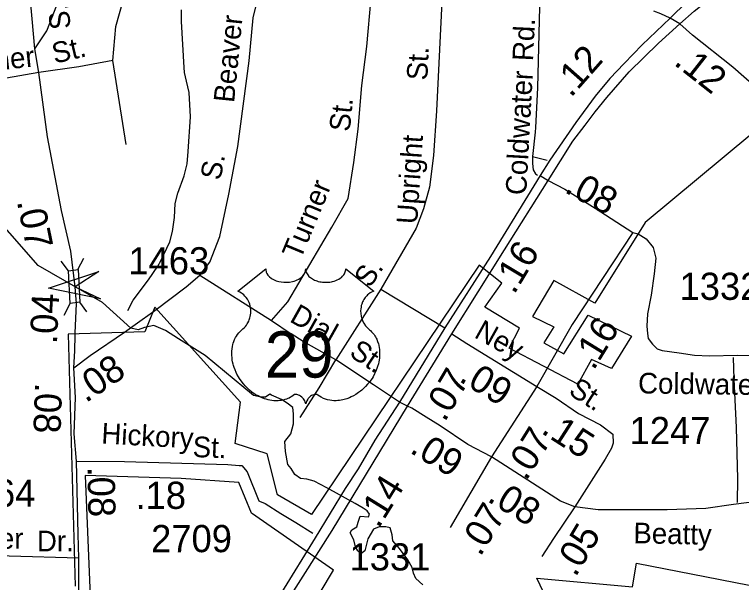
# Model space of a CAD drawing. Extents: x 1473865 to 1648260, y 639067 to 773536.
# Drawn here: x 1520496 to 1523838, y 653093 to 655704 of the extents above; entities that cross this region are included whole.
import ezdxf

# ---------------------------------------------------------------- set-up
doc = ezdxf.new("R2010")
doc.units = 0
for name, color, linetype in [('Exist Boundary Political City Limit New', 7, 'Continuous'), ('Exist Hydrographic Creek Single Shore', 7, 'Continuous'), ('Exist Hydrographic Misc Water Feature', 7, 'Continuous'), ('Exist Road Non-System Type 51', 7, 'Continuous'), ('Exist Road Non-System Type 51 Label', 7, 'Continuous'), ('Exist Road Primary US Divided Attributed', 7, 'Continuous'), ('Exist Road Primary US Mileage Hundredths English Label', 7, 'Continuous'), ('Exist Road Primary US Shield CELL', 7, 'Continuous'), ('Exist Road Primary US Shield Number Label', 7, 'Continuous'), ('Exist Road Secondary Mileage Hundredths English Label', 7, 'Continuous'), ('Exist Road Secondary Structure Standard Bridge Attributed CELL', 7, 'Continuous'), ('Exist Road Secondary Structure Standard Bridge CELL', 7, 'Continuous'), ('Exist Road Secondary Type 51 Attributed', 7, 'Continuous'), ('Exist Road Secondary Type 51 Label', 7, 'Continuous'), ('Exist Road Secondary Type 51 Number Label', 7, 'Continuous'), ('Map Preparation Boundary City Limit Buffer Line', 7, 'Continuous')]:
    doc.layers.add(name, color=color, linetype=linetype)

msp = doc.modelspace()

# ---------------------------------------------------------------- linework, layer by layer
at = {"layer": 'Exist Boundary Political City Limit New'}
for points in [[(1524121.9, 655350.9), (1523395.4, 654747.1), (1523163.5, 654376.6), (1522975.9, 654481.6), (1522877.1, 654316), (1522975.9, 654267.6), (1522929.5, 654194.9), (1523022.4, 654144.4), (1523133.2, 654322.1), (1523333, 654225.1), (1523240.9, 654076.8), (1523148.1, 654118), (1523086.2, 654004.6), (1522770.4, 654170.5), (1522818.4, 654262.4), (1522658.2, 654358.8), (1522736, 654468.6), (1522633, 654551.1), (1521862, 653404.8), (1521705.4, 653495.1), (1521656.8, 653683.9), (1521510.8, 653731.1), (1521535.6, 653922.1), (1521140.6, 654359.1), (1521094.9, 654244.4), (1520742.6, 654234.9), (1520774.1, 653074.9)], [(1521599.2, 652540.6), (1521962, 653148.8), (1521586, 653411.3), (1521526.6, 653552.1), (1521262.8, 653571.3), (1520820.8, 653584.1), (1520853.8, 652771.1)], [(1523355.1, 653181.8), (1525601.1, 652743.2), (1525601.1, 652633.6), (1526368, 652469.2), (1526258.5, 651793.1), (1526148.9, 651811.4), (1526057.6, 651190.2), (1525655.9, 651245), (1525494.5, 650399.1), (1524560.2, 650550.7), (1524669.9, 650934.4), (1524268.1, 651226.8), (1523921.2, 651482.5), (1523811.6, 651756.6), (1523683.9, 651994.1), (1523483, 652195.1), (1523318.6, 652341.2), (1523300.4, 652487.4), (1523099.5, 652688.4), (1522897.9, 653112.1), (1523336.9, 653072.1), (1523355.1, 653181.8)]]:
    msp.add_lwpolyline(points, dxfattribs=at)
at = {"layer": 'Exist Hydrographic Creek Single Shore'}
msp.add_lwpolyline([(1522373.8, 653081.1), (1522341.2, 653110.5), (1522329.7, 653135.7), (1522324.4, 653162), (1522304.5, 653196.6), (1522266.7, 653249.1), (1522235.2, 653283.7), (1522232.1, 653312.1), (1522223.7, 653343.6), (1522202.7, 653348.8), (1522172.2, 653348.8), (1522146, 653338.3), (1522120.8, 653293.2), (1522106.1, 653237.5), (1522088.2, 653223.9), (1522074.6, 653237.5), (1522064.1, 653256.4), (1522055.7, 653289), (1522038.9, 653320.5), (1522047.3, 653334.1), (1522070.4, 653348.8), (1522075.6, 653369.8), (1522085.1, 653397.1), (1522122.9, 653395), (1522128.1, 653406.6), (1522116.6, 653421.3), (1522098.7, 653434.9), (1522062, 653455.9), (1521931.8, 653528.4), (1521874.1, 653558.8), (1521839.4, 653568.2), (1521811.1, 653571.4), (1521784.8, 653589.2), (1521768, 653616.5), (1521753.3, 653635.4), (1521741.8, 653695.3), (1521738.6, 653741.5), (1521767, 653776.1), (1521778.5, 653822.3), (1521778.5, 653868.5), (1521775.4, 653896.8), (1521750.2, 653916.8), (1521723.9, 653934.6), (1521677.7, 653954.6), (1521669.3, 653957.7), (1521649.4, 653944.1), (1521629.4, 653944.1), (1521594.9, 653952.8), (1521372.2, 654136.2), (1521249.4, 654212.9), (1521189.6, 654251.7), (1521137.1, 654273.7), (1521094, 654265.3), (1521064.6, 654253.8), (1521030, 654262.2), (1520900.9, 654380.3), (1520603.9, 654550.4), (1520341.9, 654847.9)], dxfattribs=at)
at = {"layer": 'Exist Hydrographic Misc Water Feature'}
msp.add_lwpolyline([(1521016.3, 654343.5), (1521041.1, 654391.4), (1521112.6, 654484.4), (1521155.6, 654547.5), (1521168, 654571.1), (1521209.3, 654658.9), (1521222.2, 654707), (1521231.1, 654770.8), (1521234.2, 654834.8), (1521246.9, 654882.1), (1521276.2, 654961.9), (1521289, 655017.5), (1521294, 655074), (1521304.5, 655233.8), (1521298.3, 655345.5), (1521287, 655398.3), (1521277.6, 655437.9), (1521276, 655460.1), (1521263.5, 655672), (1521264.1, 655726.2)], dxfattribs=at)
at = {"layer": 'Exist Road Non-System Type 51'}
for p, q in [((1521009.4, 655107), (1520948.4, 655491.9)), ((1521348.6, 654504.9), (1521676.8, 654296.9)), ((1522180, 654441.9), (1521973.5, 654115.7)), ((1521676.8, 654296.9), (1521768.5, 654236.4))]:
    msp.add_line(p, q, dxfattribs=at)
for points in [[(1520588.6, 655546.7), (1520644.9, 655629.7), (1520701.2, 655776.8), (1520826.4, 656042.9), (1520887.4, 656144.2)], [(1520948.4, 655491.9), (1520962.4, 655648.5), (1521018.8, 655850.8)], [(1521348.6, 654504.9), (1521393.7, 654566), (1521439.9, 654683.3), (1521481.2, 654878.6), (1521523.3, 655097.8), (1521574.2, 655490.8), (1521593.8, 655688.5), (1521624, 655816)], [(1521676.8, 654296.9), (1521752.4, 654383.7), (1521955.6, 654726.4), (1522030.7, 654857.9), (1522055.8, 655024.1), (1522076.2, 655176.9), (1522092.3, 655378.2), (1522115.4, 655557.1), (1522135.4, 655782.6)], [(1522460.9, 655762.9), (1522436, 655261.3), (1522422.3, 655055.5), (1522404.4, 654910.5), (1522376.6, 654810.3), (1522343, 654721), (1522180, 654441.9)], [(1522910.5, 655738.8), (1522899.8, 655366.8), (1522891.3, 655184.8)], [(1520948.4, 655491.9), (1520792, 655463.8), (1520607.4, 655437.2)], [(1520607.4, 655437.2), (1520308.5, 655385.7), (1520196.5, 655379.7)], [(1522891.3, 655184.8), (1522890.2, 655163.1), (1522878.2, 655051.3), (1522876.8, 655019.1), (1522880.1, 654990.6), (1522892.1, 654970.8), (1522900, 654965.7)], [(1522878.2, 655051.3), (1522945, 655034.1)], [(1521051.1, 654278.1), (1521141.6, 654342.6), (1521285.7, 654452.1), (1521348.6, 654504.9)], [(1522180, 654441.9), (1522474.8, 654263.8)], [(1521973.5, 654115.7), (1521823.1, 654200.3), (1521768.5, 654236.4)], [(1521808.8, 653850.7), (1521897.2, 653986.9), (1521973.5, 654115.7)], [(1522265.7, 653921), (1522146.3, 654000.9), (1521973.5, 654115.7)], [(1523820.3, 653461), (1523821.5, 653569.1), (1523816.1, 653805.2), (1523804.4, 654027.5), (1523802.4, 654127.6)], [(1521622.3, 653465.7), (1521648.4, 653456.3), (1521720, 653409.2), (1521789.4, 653368.9), (1521867.8, 653319.6)], [(1520791.9, 653204), (1520148.7, 653223.2)]]:
    msp.add_lwpolyline(points, dxfattribs=at)
at = {"layer": 'Exist Road Primary US Divided Attributed'}
msp.add_line((1522303.4, 653903.1), (1522507.1, 654235.9), dxfattribs=at)
for points in [[(1525181.6, 656945.3), (1525079.7, 656867), (1524891.3, 656730), (1524863.9, 656708.9), (1524688.5, 656573.8), (1523832.7, 655956.7), (1523587.6, 655761.8), (1523510.8, 655686.8)], [(1523554.9, 655660.6), (1523620.9, 655718.9), (1523948.1, 655979.5), (1524703.4, 656529.4), (1524879.6, 656660.1), (1524929, 656700.6), (1525120.4, 656840.2), (1525257.2, 656942.9)], [(1523510.8, 655686.8), (1523381.6, 655565), (1523298.7, 655479), (1523232.6, 655409.7), (1523166.4, 655328.8), (1523076.1, 655207), (1522957.5, 655033.8), (1522912.4, 654964.5)], [(1522949.1, 654941.4), (1523063.5, 655122), (1523120.2, 655195.5), (1523166.4, 655256.4), (1523218.9, 655322.5), (1523322.8, 655441.2), (1523456.2, 655572.4), (1523554.9, 655660.6)], [(1522912.4, 654964.5), (1522684.5, 654590.8), (1522474.8, 654263.8), (1522265.7, 653921)], [(1522507.1, 654235.9), (1522748.6, 654622.3), (1522949.1, 654941.4)], [(1522265.7, 653921), (1522152.2, 653746.9), (1522075.6, 653614.4), (1522016.8, 653524.2), (1521878.3, 653298.4), (1521568.6, 652794.5), (1521398.5, 652533.1), (1521297.7, 652366.2), (1521268.8, 652321.8), (1521088.3, 652012.3), (1521028.9, 651896.9), (1521002.7, 651830.8), (1520907.7, 651603.9)], [(1520939.9, 651578.1), (1520985.1, 651686.6), (1521031.3, 651798.4), (1521063.6, 651873.8), (1521088.8, 651924.2), (1521125.5, 651993.5), (1521242.1, 652195.1), (1521423.7, 652490.1), (1521606.4, 652781.9), (1521955.9, 653332), (1522303.4, 653903.1)]]:
    msp.add_lwpolyline(points, dxfattribs=at)
at = {"layer": 'Exist Road Primary US Shield CELL'}
msp.add_lwpolyline([(1521650.8, 654534), (1521651.2, 654528.7), (1521652.5, 654522.4), (1521653.5, 654519.1), (1521656.4, 654512.9), (1521661.3, 654505.5), (1521668.1, 654498.3), (1521675.7, 654492), (1521680.9, 654488.6), (1521689.7, 654483.9), (1521699.6, 654479.7), (1521710.7, 654476.5), (1521722, 654474.3), (1521734.4, 654472.9), (1521746.6, 654472.7), (1521759.9, 654473.7), (1521774.4, 654476.5), (1521781.2, 654478.2), (1521788.7, 654480.8), (1521795.7, 654483.7), (1521803.4, 654487.8), (1521809.5, 654491.7), (1521814.4, 654495.2), (1521821.2, 654501.8), (1521826.6, 654508.5), (1521828.9, 654512.3), (1521830.9, 654516), (1521833.6, 654523.7), (1521834.3, 654527.1), (1521834.9, 654534.3), (1521835.3, 654528.3), (1521835.9, 654524.6), (1521836.9, 654520.9), (1521838.4, 654517), (1521841.2, 654511.6), (1521844.2, 654507), (1521849.9, 654500.2), (1521853.5, 654496.9), (1521856.8, 654494.2), (1521865.5, 654488.2), (1521875.7, 654483.1), (1521880.7, 654480.9), (1521885.9, 654479), (1521892.4, 654477.1), (1521899.2, 654475.5), (1521905.9, 654474.3), (1521912.7, 654473.3), (1521919.7, 654472.8), (1521925.4, 654472.7), (1521932.4, 654472.7), (1521938.8, 654473.1), (1521945.4, 654473.9), (1521952.7, 654475.1), (1521958.6, 654476.4), (1521966.3, 654478.4), (1521973.3, 654480.9), (1521979.5, 654483.6), (1521987.4, 654487.8), (1521993.9, 654491.8), (1521998.6, 654495.6), (1522004.2, 654500.8), (1522009.5, 654506.9), (1522012.7, 654511.4), (1522014.9, 654516.1), (1522016.9, 654520.9), (1522018.2, 654526.1), (1522018.8, 654530.6), (1522018.9, 654534.4), (1522147.5, 654432), (1522144.5, 654430.8), (1522137.5, 654427.4), (1522131.9, 654424.1), (1522123.1, 654417.9), (1522119.3, 654414.5), (1522115.5, 654410.9), (1522112, 654407.1), (1522108.9, 654403.5), (1522105.2, 654398.3), (1522101.9, 654393.2), (1522098.6, 654387.5), (1522096.2, 654382.5), (1522092.2, 654372.2), (1522090.3, 654365.7), (1522089.1, 654360.1), (1522087.6, 654348.7), (1522087.2, 654343.2), (1522087.2, 654337.8), (1522087.5, 654332.1), (1522088.1, 654326.6), (1522089.1, 654320.9), (1522090, 654315.9), (1522091.6, 654309.7), (1522093.8, 654302.6), (1522096.6, 654295.7), (1522102.5, 654284.5), (1522110.1, 654273.1), (1522115.5, 654266.7), (1522120.8, 654261.3), (1522128.7, 654254.6), (1522133, 654250.8), (1522138, 654245.8), (1522146, 654236.5), (1522149.3, 654232.1), (1522152.6, 654227.1), (1522155.6, 654222.1), (1522158.7, 654216.6), (1522161.1, 654211.8), (1522165.6, 654200.8), (1522168.9, 654190.1), (1522170.4, 654184.4), (1522172.8, 654171.8), (1522173.7, 654165.6), (1522174.7, 654153.3), (1522174.8, 654138.4), (1522173.6, 654124.3), (1522171, 654107.8), (1522168.8, 654097.9), (1522165.4, 654086.4), (1522162.1, 654076.5), (1522156.2, 654061.8), (1522151, 654051.2), (1522144.3, 654038.7), (1522139.6, 654031.2), (1522134.2, 654023.1), (1522127.5, 654013.9), (1522119.6, 654004), (1522110.1, 653993.6), (1522102.4, 653985.9), (1522092.4, 653976.9), (1522086.3, 653971.9), (1522077.7, 653965.4), (1522065.8, 653957.5), (1522054.1, 653950.7), (1522044.2, 653945.6), (1522035.4, 653941.8), (1522024, 653937.5), (1522005, 653932.2), (1521998.1, 653930.8), (1521989.9, 653929.6), (1521982.2, 653928.8), (1521974.8, 653928.4), (1521964.7, 653928.4), (1521954.8, 653929.1), (1521945.4, 653930.5), (1521935.6, 653932.5), (1521925.3, 653935.6), (1521916, 653939.2), (1521906.6, 653943.9), (1521890.7, 653953.9), (1521886.1, 653956.3), (1521883.5, 653957), (1521877.4, 653957.3), (1521871.6, 653956.1), (1521865.7, 653953.7), (1521862.1, 653951.8), (1521857.3, 653948.7), (1521853.7, 653945.8), (1521849.3, 653941.7), (1521846.3, 653938.2), (1521843.9, 653935.4), (1521839.5, 653928.4), (1521837.9, 653925), (1521836.2, 653920.7), (1521834.7, 653914.3), (1521832.7, 653922.4), (1521830.3, 653927.7), (1521827.6, 653932.2), (1521824.8, 653936.3), (1521820.3, 653941.4), (1521816.3, 653945.3), (1521811.4, 653949.3), (1521806.2, 653952.4), (1521802.1, 653954.5), (1521798.3, 653956), (1521793.7, 653957.1), (1521789.9, 653957.4), (1521786.7, 653957.3), (1521782.5, 653956.3), (1521776.6, 653952.2), (1521771.1, 653948.4), (1521765.1, 653944.6), (1521758, 653940.8), (1521752.8, 653938.4), (1521746.5, 653936), (1521739.2, 653933.5), (1521731.3, 653931.5), (1521723.2, 653929.9), (1521716.1, 653928.7), (1521708.4, 653928.1), (1521701.5, 653927.8), (1521694.3, 653927.9), (1521687.5, 653928.4), (1521679.7, 653929.1), (1521670, 653930.6), (1521661.9, 653932.4), (1521653.4, 653934.7), (1521644.7, 653937.4), (1521635.3, 653941), (1521623.7, 653946.1), (1521615.5, 653950.3), (1521602.7, 653957.6), (1521587.7, 653968), (1521576.3, 653977.2), (1521568, 653984.8), (1521555.8, 653997.2), (1521548.6, 654005.3), (1521537.3, 654019.9), (1521530.1, 654030.5), (1521525.4, 654038.2), (1521518.6, 654050.7), (1521514.8, 654058.5), (1521510, 654069.9), (1521506.1, 654080.3), (1521502.9, 654090.2), (1521501.2, 654096.5), (1521498.8, 654107.5), (1521497.3, 654115.4), (1521495.9, 654126.1), (1521495.1, 654137.4), (1521494.9, 654147.8), (1521495.2, 654156.5), (1521496.2, 654166.6), (1521497.9, 654177.3), (1521499.9, 654186.5), (1521501.8, 654193.1), (1521504.5, 654201.2), (1521508.1, 654210.1), (1521512.4, 654218.6), (1521516.5, 654225.6), (1521521.5, 654233.2), (1521526.6, 654239.7), (1521533.1, 654246.8), (1521540, 654253.4), (1521546.2, 654258.5), (1521553.7, 654265.7), (1521557.5, 654270.2), (1521562.2, 654276.3), (1521565.9, 654282), (1521568.9, 654287.1), (1521572.8, 654294.6), (1521575.2, 654300.2), (1521578.1, 654308.9), (1521579.6, 654315), (1521581.1, 654322.8), (1521582.1, 654330.2), (1521582.5, 654339.4), (1521582.3, 654347), (1521581.3, 654355.9), (1521579.6, 654364.4), (1521577.6, 654371.8), (1521574.4, 654380.3), (1521571.5, 654386.6), (1521566.5, 654395), (1521561.1, 654402.8), (1521555.4, 654409.2), (1521549.7, 654414.9), (1521544.3, 654419.2), (1521539.1, 654422.9), (1521532.5, 654426.8), (1521526.2, 654430), (1521522.3, 654431.5)], close=True, dxfattribs=at)
at = {"layer": 'Exist Road Secondary Structure Standard Bridge Attributed CELL'}
msp.add_lwpolyline([(1520891.7, 654396.6), (1520652.8, 654445.4), (1520884.1, 654522.6), (1520774.5, 654452.7)], close=True, dxfattribs=at)
at = {"layer": 'Exist Road Secondary Structure Standard Bridge CELL'}
for p, q in [((1520787.1, 654531.3), (1520814.8, 654584)), ((1520744.1, 654525.3), (1520711.1, 654569.8)), ((1520828.9, 654336.4), (1520795.9, 654380.8)), ((1520724.2, 654322), (1520752, 654374.8))]:
    msp.add_line(p, q, dxfattribs=at)
msp.add_lwpolyline([(1520752, 654374.8), (1520743.9, 654525.3), (1520787.9, 654531.4), (1520795.9, 654380.8)], close=True, dxfattribs=at)
at = {"layer": 'Exist Road Secondary Type 51 Attributed'}
for p, q in [((1522897.7, 653993.4), (1522689.4, 653670.5)), ((1522689.4, 653670.5), (1522499, 653345.8))]:
    msp.add_line(p, q, dxfattribs=at)
for points in [[(1520774.5, 654452.7), (1520754.6, 654615.7), (1520711.2, 654803.5), (1520648.1, 655141.5), (1520607.4, 655437.2), (1520588.6, 655546.7), (1520562.6, 655841), (1520559.6, 656009.1), (1520562.1, 656143.1), (1520585.2, 656286.3), (1520616.2, 656376.2), (1520657.8, 656463.4), (1520723.7, 656576.1), (1520859, 656755.7), (1521079.7, 657019.7), (1521165.2, 657104.3), (1521510.5, 657408)], [(1523510.8, 655686.8), (1523467.7, 655707.8), (1523435.5, 655719.6)], [(1523554.9, 655660.6), (1523510.8, 655686.8)], [(1525243, 654335.7), (1525131.7, 654392.4), (1525001.5, 654461.7), (1524943.8, 654501.6), (1524839.9, 654580.3), (1524681.3, 654710.5), (1524475.6, 654883.7), (1524404.2, 654946.7), (1524164.8, 655148.3), (1523989.5, 655295.2), (1523799.3, 655462.7), (1523613, 655609.2), (1523554.9, 655660.6)], [(1522912.4, 654964.5), (1522949.1, 654941.4)], [(1522949.1, 654941.4), (1523026.8, 654901.5), (1523166.4, 654814.4), (1523338.6, 654702.1)], [(1523338.6, 654702.1), (1523059.2, 654279.5), (1522897.7, 653993.4)], [(1523338.6, 654702.1), (1523363.2, 654695.5)], [(1523363.2, 654695.5), (1523400.8, 654673.2), (1523432, 654632.7), (1523445, 654584.4), (1523437.3, 654512.1), (1523422.6, 654413.4), (1523406.8, 654327.3), (1523403.7, 654271.6), (1523405.8, 654237), (1523408.9, 654213.9), (1523428.9, 654188.7), (1523450.4, 654167.5), (1523473.1, 654159.9), (1523552.7, 654148.2), (1523622, 654138.3), (1523691.3, 654135.2), (1523818.4, 654137.3), (1524124, 654136.2), (1524319, 654129.5), (1524496, 654120), (1524725.8, 654115.6), (1524953.7, 654105.2), (1525107.6, 654099.5)], [(1520769.2, 654079.3), (1520772.5, 654157.3), (1520775.3, 654230.1), (1520775.3, 654239.5), (1520781.6, 654375.9), (1520774.5, 654452.7)], [(1520769.2, 654079.3), (1520844.1, 654136.1), (1521002, 654243.1), (1521051.1, 654278.1)], [(1522507.1, 654235.9), (1522576.3, 654191.5), (1522897.7, 653993.4)], [(1520781.3, 653650.2), (1520770.3, 653776.5), (1520776.9, 653942.7), (1520769.2, 654079.3)], [(1525107.6, 654099.5), (1524977.4, 653881.1), (1524931.2, 653797.1), (1524887.1, 653739.4), (1524850.4, 653711), (1524815.7, 653693.2), (1524764.3, 653682.7), (1524594.2, 653650.1), (1524506, 653622.8), (1524289.7, 653538.9), (1524199.5, 653507.4), (1524136.3, 653494.9), (1524065.1, 653484.3), (1523801.6, 653450.7), (1523674.5, 653432.8), (1523497.1, 653426.5), (1523310.2, 653426.5), (1523180.1, 653426.5), (1523071.9, 653440.2)], [(1522897.7, 653993.4), (1522986.8, 653939.4), (1523089.4, 653869.3), (1523190.8, 653817.6), (1523247.2, 653774.6), (1523248, 653733.5), (1523241.5, 653710.3), (1523212.3, 653659.2), (1523071.9, 653440.2)], [(1522303.4, 653903.1), (1522265.7, 653921)], [(1522689.4, 653670.5), (1522580.9, 653727.2), (1522453.4, 653812.8), (1522389, 653853.1), (1522322.1, 653894.4), (1522303.4, 653903.1)], [(1520781.3, 653650.2), (1521001.2, 653648.7), (1521476.3, 653634.8), (1521529.4, 653630.3), (1521541.8, 653630.2), (1521566.2, 653601.9), (1521620, 653468.1), (1521622.3, 653465.7)], [(1520791.9, 653204), (1520788.5, 653315.4), (1520781.3, 653650.2)], [(1523071.9, 653440.2), (1523005.8, 653466.4), (1522689.4, 653670.5)], [(1523071.9, 653440.2), (1522973.7, 653294.8), (1522920.1, 653211.6)], [(1520802.5, 652708.8), (1520800.7, 652828.9), (1520790.9, 653067), (1520791.9, 653204)]]:
    msp.add_lwpolyline(points, dxfattribs=at)
at = {"layer": 'Map Preparation Boundary City Limit Buffer Line'}
for points in [[(1524121.9, 655350.9), (1523395.4, 654747.1), (1523163.5, 654376.6), (1522975.9, 654481.6), (1522877.1, 654316), (1522975.9, 654267.6), (1522929.5, 654194.9), (1523022.4, 654144.4), (1523133.2, 654322.1), (1523333, 654225.1), (1523240.9, 654076.8), (1523148.1, 654118), (1523086.2, 654004.6), (1522770.4, 654170.5), (1522818.4, 654262.4), (1522658.2, 654358.8), (1522736, 654468.6), (1522633, 654551.1), (1521862, 653404.8), (1521705.4, 653495.1), (1521656.8, 653683.9), (1521510.8, 653731.1), (1521535.6, 653922.1), (1521140.6, 654359.1), (1521094.9, 654244.4), (1520742.6, 654234.9), (1520774.1, 653074.9)], [(1521599.2, 652540.6), (1521962, 653148.8), (1521586, 653411.3), (1521526.6, 653552.1), (1521262.8, 653571.3), (1520820.8, 653584.1), (1520853.8, 652771.1)], [(1523355.1, 653181.8), (1525601.1, 652743.2), (1525601.1, 652633.6), (1526368, 652469.2), (1526258.5, 651793.1), (1526148.9, 651811.4), (1526057.6, 651190.2), (1525655.9, 651245), (1525494.5, 650399.1), (1524560.2, 650550.7), (1524669.9, 650934.4), (1524268.1, 651226.8), (1523921.2, 651482.5), (1523811.6, 651756.6), (1523683.9, 651994.1), (1523483, 652195.1), (1523318.6, 652341.2), (1523300.4, 652487.4), (1523099.5, 652688.4), (1522897.9, 653112.1), (1523336.9, 653072.1), (1523355.1, 653181.8)]]:
    msp.add_lwpolyline(points, dxfattribs=at)

# ---------------------------------------------------------------- texts
at = {"layer": 'Exist Road Non-System Type 51 Label'}
for s, rotation, p in [('Beaver', 84.3384, (1521505.4, 655295.9)), ('Rd.', 87.2217, (1522879.8, 655488.2)), ('St.', 13.1622, (1520680.4, 655477.5)), ('Corriher', 6.1332, (1520135.8, 655416.6)), ('St.', 87.1539, (1522393.6, 655399.6)), ('Coldwater', 86.8859, (1522848.4, 654872)), ('St.', 84.2682, (1522037.1, 655162.9)), ('Upright', 86.1744, (1522347, 654738.2)), ('S.', 79.1443, (1521442.6, 654938.5)), ('Turner', 67.379, (1521810.7, 654572.9)), ('S.', 56.1524, (1522129.8, 654443)), ('Dial', 330.6147, (1521756, 654294.6)), ('St.', 326.1339, (1522030, 654137))]:
    msp.add_text(s, height=95, rotation=rotation, dxfattribs=at).set_placement(p)
for s, p in [('Sprinkler', (1520035.9, 653247.7)), ('Dr.', (1520598.9, 653235.7))]:
    msp.add_text(s, height=95, dxfattribs=at).set_placement(p)
at = {"layer": 'Exist Road Primary US Mileage Hundredths English Label'}
for s, rotation, p in [('.12', 48.5826, (1523053.9, 655318.6)), ('.16', 58.9576, (1522793.2, 654413.2)), ('.07', 59.4209, (1522473.8, 653826.6)), ('.14', 58.2803, (1522169.9, 653337.1))]:
    msp.add_text(s, height=125, rotation=rotation, dxfattribs=at).set_placement(p)
at = {"layer": 'Exist Road Primary US Shield Number Label'}
msp.add_text('29', height=212.5, dxfattribs=at).set_placement((1521646.6, 654034.7))
at = {"layer": 'Exist Road Secondary Mileage Hundredths English Label'}
for s, rotation, p in [('.12', 321.8277, (1523522.6, 655476.5)), ('.08', 331.2855, (1523019.5, 654889.4)), ('.07', 281.357, (1520506.3, 654844.9)), ('.04', 87.3626, (1520690.8, 654186.8)), ('.16', 58.408, (1523158.6, 654064)), ('.08', 34.1512, (1520823.6, 653915.9)), ('.09', 328.4927, (1522534.5, 654020.8)), ('.08', 268.0606, (1520590.3, 654012.3)), ('.07', 57.9545, (1522848.3, 653555.9)), ('.15', 327.2992, (1522912.4, 653782.3)), ('.09', 328.7978, (1522308.4, 653692.3)), ('.08', 271.2169, (1520831.1, 653624.4)), ('.18', 0.3115, (1521052.3, 653430)), ('.08', 328.5379, (1522664.5, 653468.8)), ('.07', 58.2938, (1522637.3, 653207.8)), ('.05', 59.0139, (1523075.3, 653113.7))]:
    msp.add_text(s, height=125, rotation=rotation, dxfattribs=at).set_placement(p)
at = {"layer": 'Exist Road Secondary Type 51 Label'}
for s, rotation, p in [('S.', 97.6237, (1520756, 655641.9)), ('Ney', 330.8152, (1522604.7, 654221.9)), ('Coldwater', 359.1988, (1523362.4, 653962.1)), ('St.', 327.2992, (1523038.5, 653960.4)), ('Hickory', 356.8565, (1520893.5, 653731.6)), ('St.', 357.7537, (1521313.6, 653669.7)), ('Beatty', 358.8439, (1523340.7, 653273.2))]:
    msp.add_text(s, height=95, rotation=rotation, dxfattribs=at).set_placement(p)
at = {"layer": 'Exist Road Secondary Type 51 Number Label'}
for s, p in [('1463', (1521019.4, 654509.1)), ('1332', (1523553.6, 654392)), ('1247', (1523323.9, 653728.6)), ('1464', (1520219.8, 653441)), ('2709', (1521123.9, 653231.9)), ('1331', (1522036.3, 653147.8))]:
    msp.add_text(s, height=125, dxfattribs=at).set_placement(p)

doc.saveas('drawing.dxf')
